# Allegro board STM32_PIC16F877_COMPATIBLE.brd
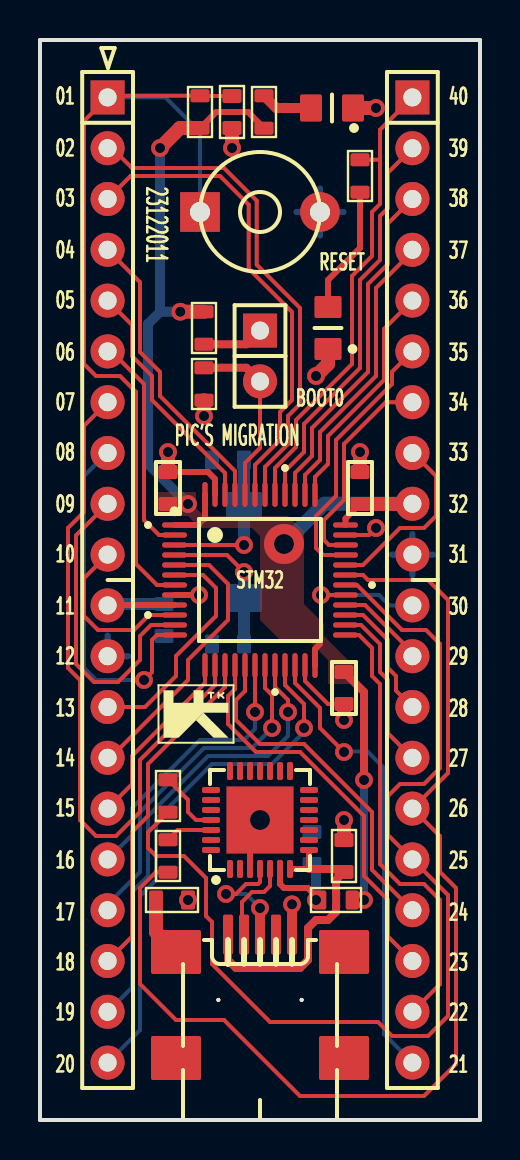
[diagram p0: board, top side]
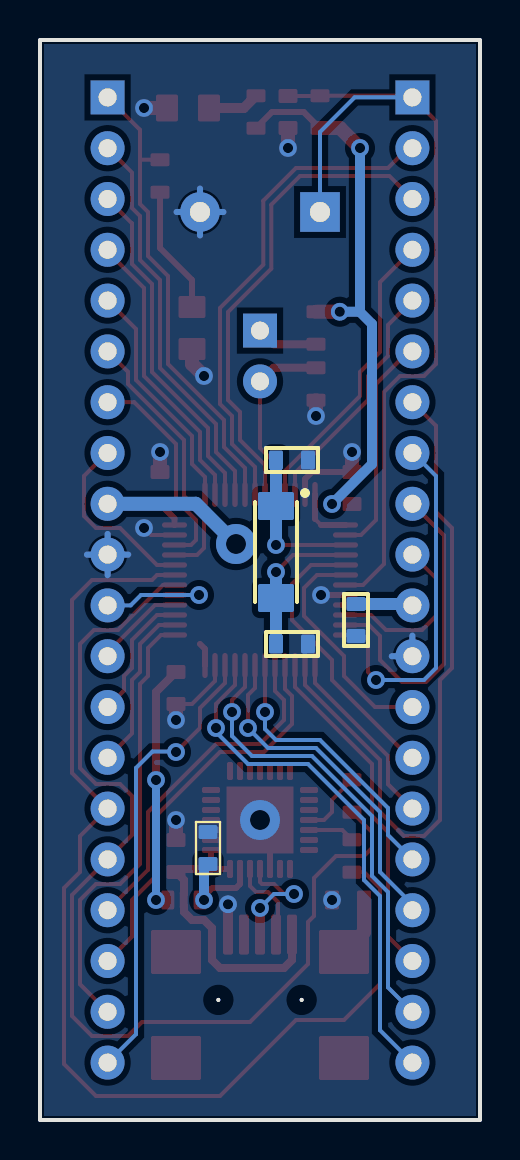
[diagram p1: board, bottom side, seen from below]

Outline 22 x 54 mm; copper layers: TOP, BOTTOM. Coordinates in mm from the lower left corner of the outline.
Outline path: 0,54 0,0 22,0 22,54 0,54

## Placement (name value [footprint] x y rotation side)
C1  100n  [CAP0603_B]  6.4 31.6 90 top
C2  100n  [CAP0603_B]  16 31.6 90 top
C3  100n  [CAP0603_B]  15.2 21.6 270 top
C4  100n  [CAP0603_B]  6.2 25 270 bottom
C5  15p  [CAP0603_B]  9.4 23.8 180 bottom
C6  15p  [CAP0603_B]  9.4 33 180 bottom
C7  10u  [CAP0603_B1]  13.6 13.6 90 bottom
C8  100n  [CAP0603_B1]  6.6 11 0 top
C9  10u  [CAP0603_B1]  15.2 13.2 90 top
C10  100n  [CAP0603_B1]  9.6 50.4 270 top
D1  LED  [LEDC2012X120M]  14.6 50.6 180 top
D2  LED  [LEDC2012X120M]  14.4 39.6 90 top
J1  CON20  [HDR254M-1X20]  3.38 51.13 270 top
J2  CON20  [HDR254M-1X20]  18.62 51.13 270 top
J3  USB_MB  [HIROSE-US60-MB-5ST]  11 0 0 top
J4  CON2  [HDR254M-1X2]  11 39.47 270 top
NOREF  -  []  5.92 18.86 0 top
NOREF#2  -  []  24 0 90 top
NOREF#3  -  []  0 56 0 top
R1  39R  [RES0603_B1]  6.4 13.2 270 top
R2  39R  [RES0603_B1]  6.4 16.2 270 top
R3  330R  [RES0603_B1]  11.2 50.4 90 top
R4  0R  [RES0603_B1]  14.8 11 0 top
R5  1K  [RES0603_B1]  8.2 39.6 270 top
R6  10K  [RES0603_B1]  8.2 36.8 270 top
R7  10K  [RES0603_B1]  8 50.4 90 top
R8  330R  [RES0603_B1]  16 47.2 270 top
S1  BT  [BUTTON_RST_CIRCLE]  11 45.4 0 top
U1  STM32F100  [LQFP48L]  11 27 0 top
U2  -  [CP2102]  11 15 90 top
Y1  32.768KHz  [ABS10]  10.2 28.4 270 bottom

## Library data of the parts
C1-C10 = C1005_0: User Part Number: pn; Tolerance: RichardLC
D1 D2 = LED_0: User Part Number: pn; Tolerance: RichardLC
J1 J2 = CON20: User Part Number: pn; Tolerance: RichardLC
J3 = CON9_2: User Part Number: pn; Tolerance: RichardLC
J4 = CON2: User Part Number: pn; Tolerance: RichardLC
R1-R8 = R_0: User Part Number: pn; Tolerance: RichardLC
S1 = SW PUSHBUTTON_1: User Part Number: pn; Tolerance: RichardLC
U1 = STM32F100_1: User Part Number: pn; Tolerance: RichardLC
U2 = CP2102_2: User Part Number: pn; Tolerance: RichardLC
Y1 = ZTA: User Part Number: pn; Tolerance: RichardLC

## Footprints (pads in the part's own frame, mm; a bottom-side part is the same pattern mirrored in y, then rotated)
ABS10
  custom 0.35x0.35 smd: 1(-2.3,0) 2(2.3,0)
BUTTON_RST_CIRCLE
  rect 1.98x1.98 hole 1: 1(-3,0)
  round 1.98 hole 1: 2(3,0)
CAP0603_B
  custom 0.175x0.175 smd: 1(-0.8,0) 2(0.8,0)
CAP0603_B1
  custom 0.175x0.175 smd: 1(-0.8,0) 2(0.8,0)
CP2102
  custom 0.075x0.075 smd: 1(-2.45,1.5) 2(-2.45,1) 3(-2.45,0.5) 4(-2.45,0) 5(-2.45,-0.5) 6(-2.45,-1) 7(-2.45,-1.5) 8(-1.5,-2.45) 9(-1,-2.45) 10(-0.5,-2.45) 11(0,-2.45) 12(0.5,-2.45) 13(1,-2.45) 14(1.5,-2.45) 15(2.45,-1.5) 16(2.45,-1) 17(2.45,-0.5) 18(2.45,0) 19(2.45,0.5) 20(2.45,1) 21(2.45,1.5) 22(1.5,2.45) 23(1,2.45) 24(0.5,2.45) 25(0,2.45) 26(-0.5,2.45) 27(-1,2.45) 28(-1.5,2.45)
  rect 3.35x3.35 smd: 29(0,0)
HDR254M-1X2
  rect 1.7x1.7 hole 0.9: 1(0,0)
  round 1.7 hole 0.9: 2(2.54,0)
HDR254M-1X20
  rect 1.7x1.7 hole 0.9: 1(0,0)
  round 1.7 hole 0.9: 2(2.54,0) 3(5.08,0) 4(7.62,0) 5(10.16,0) 6(12.7,0) 7(15.24,0) 8(17.78,0) 9(20.32,0) 10(22.86,0) 11(25.4,0) 12(27.94,0) 13(30.48,0) 14(33.02,0) 15(35.56,0) 16(38.1,0) 17(40.64,0) 18(43.18,0) 19(45.72,0) 20(48.26,0)
HIROSE-US60-MB-5ST
  round 0.2 hole 0.9 unplated: (-2.083,6.005) (2.083,6.005)
  custom 0.125x0.125 smd: 1(-1.6,9.271) 2(-0.8,9.271) 3(0,9.271) 4(0.8,9.271) 5(1.6,9.271)
  custom 0.55x0.55 smd: 6(-4.2,3.1) 7(4.2,3.1) 8(-4.2,8.4) 9(4.2,8.4)
LEDC2012X120M
  custom 0.275x0.275 smd: A(1.05,0) C(-1.05,0)
LQFP48L
  oval 1.25x0.27 smd: 1(-4.275,2.75) 2(-4.275,2.25) 3(-4.275,1.75) 4(-4.275,1.25) 5(-4.275,0.75) 6(-4.275,0.25) 7(-4.275,-0.25) 8(-4.275,-0.75) 9(-4.275,-1.25) 10(-4.275,-1.75) 11(-4.275,-2.25) 12(-4.275,-2.75) 25(4.275,-2.75) 26(4.275,-2.25) 27(4.275,-1.75) 28(4.275,-1.25) 29(4.275,-0.75) 30(4.275,-0.25) 31(4.275,0.25) 32(4.275,0.75) 33(4.275,1.25) 34(4.275,1.75) 35(4.275,2.25) 36(4.275,2.75)
  oval 0.27x1.25 smd: 13(-2.75,-4.275) 14(-2.25,-4.275) 15(-1.75,-4.275) 16(-1.25,-4.275) 17(-0.75,-4.275) 18(-0.25,-4.275) 19(0.25,-4.275) 20(0.75,-4.275) 21(1.25,-4.275) 22(1.75,-4.275) 23(2.25,-4.275) 24(2.75,-4.275) 37(2.75,4.275) 38(2.25,4.275) 39(1.75,4.275) 40(1.25,4.275) 41(0.75,4.275) 42(0.25,4.275) 43(-0.25,4.275) 44(-0.75,4.275) 45(-1.25,4.275) 46(-1.75,4.275) 47(-2.25,4.275) 48(-2.75,4.275)
RES0603_B1
  custom 0.163x0.163 smd: 1(-0.812,0) 2(0.812,0)

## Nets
GND: C1.2 C2.2 C3.2 C4.2 C5.2 C6.2 C7.2 C8.2 C9.2 C10.2 D1.C D2.C J1.12 J2.10 J3.5(GND) R6.2 S1.2 U1.8(VSSA) U1.23(VSS_1) U1.35(VSS_2) U1.47(VSS_3) U2.3(GND) U2.29(TM)
VDD1: C4.1 J1.11 U1.9(VDDA)
VDD2: C1.1 C2.1 C3.1 J2.9 R3.1 R4.2 R5.1 R7.1 U1.1(VBAT) U1.24(VDD_1) U1.36(VDD_2) U1.48(VDD_3)
BOOT0: J4.2 R6.1 U1.44(BOOT0)
NRST: C10.1 J1.1 R7.2 S1.1 U1.7(NRST)
OSC32_IN: C6.1 U1.3(PC14/OSC32_IN) Y1.1
OSC32_OUT: C5.1 U1.4(PC15/OSC32_OUT) Y1.2
OSC_IN: J1.14 U1.5(PD0/OSC_IN)
OSC_OUT: J1.13 U1.6(PD1/OSC_OUT)
PA0: J1.10 U1.10(PA0/WKUP)
PA1: J1.9 U1.11(PA1)
PA2: J1.8 U1.12(PA2)
PA3: J1.15 U1.13(PA3)
PA4: J1.7 U1.14(PA4)
PA5: J1.18 U1.15(PA5)
PA6: J2.18 U1.16(PA6)
PA7: J2.17 U1.17(PA7)
PA8: J2.11 U1.29(PA8)
PA9: J2.16 R2.2 U1.30(PA9)
PA10: J2.15 R1.2 U1.31(PA10)
PA11: J2.8 U1.32(PA11)
PA12: J2.6 U1.33(PA12)
PA13: J2.7 U1.34(PA13)
PA14: J2.5 U1.37(PA14)
PA15: J2.4 U1.38(PA15)
PB0: J1.16 U1.18(PB0)
PB1: J1.17 U1.19(PB1)
PB2: J1.19 U1.20(PB2)
PB3: J2.3 U1.39(PB3)
PB4: J2.2 U1.40(PB4)
PB5: J2.1 R8.1 U1.41(PB5)
PB6: J1.2 U1.42(PB6)
PB7: J1.3 U1.43(PB7)
PB8: J1.4 U1.45(PB8)
PB9: J1.5 U1.46(PB9)
PB10: J1.20 U1.21(PB10)
PB11: J2.20 U1.22(PB11)
PB12: J2.19 U1.25(PB12)
PB13: J2.14 U1.26(PB13)
PB14: J2.13 U1.27(PB14)
PB15: J2.12 U1.28(PB15)
PC13: J1.6 U1.2(PC13/TAMPER/RTC)
UART_3V3: C7.1 R4.1 U2.6(VDD)
N15023592: C9.1 J3.1(VBUS) U2.7(REGIN) U2.8(VBUS)
N15023612: J3.3(DP) U2.4(D+)
N15023760: R1.1 U2.26(TXD)
N15023764: R2.1 U2.25(RXD)
N15029027: C8.1 J3.8(SH3)
N15029202: J4.1 R5.2
N15033163: J3.2(DM) U2.5(D-)
N150239201: D1.A R3.2
N150311720: D2.A R8.2

Pads without a net: J3 4 6 7 9; U2 1 2 9 10 11 12 13 14 15 16 17 18 19 20 21 22 23 24 27 28

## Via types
v1: diameter 0.889, hole 0.508, TOP to BOTTOM, 29 vias
v2: diameter 2, hole 1, TOP to BOTTOM, 2 vias

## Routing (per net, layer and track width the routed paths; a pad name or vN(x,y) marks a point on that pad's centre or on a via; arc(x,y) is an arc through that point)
GND: length 32.7
  TOP w0.2: v1(16.8,29.6) 16.45,29.25 U1.35 ; C3.2 14.4,20.8 13.25,21.95 U1.23
  TOP w0.3: C1.2 8.4,32.4 8.75,32.05 U1.47 ; v2(11,15) 10.5,14.5 U2.3 ; U1.8 v1(7.95,26.25)
  TOP w0.5: J3.5 v1(12.6,10.79)
  TOP w0.7: C3.2 v1(15.2,20) ; C1.2 v1(6.4,33.4) ; C10.2 v1(9.6,48.6) ; D2.C 14.4,37.8 v1(13.8,37.2) ; D1.C v1(16.8,50.6) ; C2.2 v1(16,33.4) ; C9.2 v1(15.2,15) ; R6.2 v1(8.2,35.2)
  BOTTOM w0.305: J2.10 18.62,29.3 ; J2.10 19.65,28.27 ; J2.10 18.62,27.24 ; J2.10 17.59,28.27 ; 12.83,45.4 S1.2 ; S1.2 14,44.23 ; S1.2 14,46.57 ; S1.2 15.17,45.4 ; 3.38,24.22 J1.12 4.41,23.19
  vias: v1(7.4,11)
VDD1: length 6.2
  TOP w0.3: U1.9 3.4,25.75 J1.11
  BOTTOM w0.6: C4.1 3.45,25.8 J1.11
VDD2: length 55.1
  TOP w0.2: 7.95,29.75 8.25,30.05
  TOP w0.3: 8.25,30.05 U1.48 ; U1.36 15.28,30.07 C2.1 ; U1.24 13.75,23.55 14,23.8 ; U1.1 7.95,29.75 ; R7.1 8.81,50.4 10.4,50.4 11.2,49.6 R3.1
  TOP w0.4: v1(16.2,17) 16.2,21.4 C3.1
  TOP w0.5: R4.2 v1(16.2,11)
  TOP w0.7: J2.9 18.61,30.8 C2.1 ; v1(6,48.6) 7,49.6 7.99,49.6 R7.1 ; R5.1 v1(7.01,40.41)
  BOTTOM w0.2: 6,40.4 6.01,40.41
  BOTTOM w0.4: v1(16.2,11) v1(16.2,17)
  BOTTOM w0.5: v1(6,48.6) 6,40.4 5.4,39.8 5.4,32.8 v1(7.4,30.8) ; 6.01,40.41 v1(7.01,40.41)
  BOTTOM w0.7: v2(12.2,28.8) 14.21,30.81 J2.9
BOOT0: length 9
  TOP w0.2: U1.44 10.25,32.85 11,33.6 J4.2
  TOP w0.4: J4.2 10.32,37.61 R6.1
NRST: length 43.6
  TOP w0.2: C10.1 8.01,51.2 R7.2 3.46,51.21 J1.1 2.2,49.95 2.2,37.8 2.8,37.2 4,37.2 4.8,36.4 4.8,27.8 5.85,26.75 U1.7
  BOTTOM w0.2: S1.1 8,49.4 6.27,51.13 J1.1
OSC32_IN: length 7.7
  TOP w0.2: U1.3 v1(10.2,28.75)
  BOTTOM w0.6: v1(10.2,28.75) Y1.1 C6.1
OSC32_OUT: length 7.4
  TOP w0.2: U1.4 9.35,28.25 v1(10.2,27.4)
  BOTTOM w0.6: C5.1 Y1.2 v1(10.2,27.4)
OSC_IN: length 14.3
  TOP w0.2: J1.14 3.51,18.11 7.4,22 7.4,23 9.4,25 9.4,26.8 8.45,27.75 U1.5
OSC_OUT: length 11.6
  TOP w0.2: J1.13 5.25,20.65 6.8,22.2 6.8,23.2 8.8,25.2 8.8,26.6 8.15,27.25 U1.6
PA0: length 8.7
  TOP w0.2: J1.10 2.2,27.09 2.2,25.2 2.9,24.5 4.7,24.5 5.45,25.25 U1.10
PA1: length 15.8
  TOP w0.2: U1.11 5.55,24.75 5,24.2 5,23 3.9,21.9 2.7,21.9 1.8,22.8 1.8,29.23 J1.9
PA2: length 17.9
  TOP w0.2: U1.12 5.85,24.25 5.6,24 5.6,22.4 v1(5.2,22)
  BOTTOM w0.2: J1.8 3.35,33.35 2.2,32.2 2.2,22.6 2.8,22 v1(5.2,22)
PA3: length 9.2
  TOP w0.2: U1.13 8.25,21.85 4.6,18.2 4.6,16.79 J1.15
PA4: length 34.7
  TOP w0.2: J1.7 2.2,34.71 2.2,30.4 1.4,29.6 1.4,22.6 2,22 2,15 2.8,14.2 3.8,14.2 5,15.4 5,18 8.75,21.75 U1.14
PA5: length 17.2
  TOP w0.2: J1.18 4.6,9.17 4.6,14.4 5.4,15.2 5.4,17.8 9.25,21.65 U1.15
PA6: length 20
  TOP w0.2: U1.16 9.75,21.55 9.4,21.2 9.4,19.8 10.8,18.4 13,18.4 16.2,15.2 16.2,12.2 17.4,11 17.4,9.17 J2.18
PA7: length 17.4
  TOP w0.2: U1.17 10.25,21.45 9.8,21 9.8,20 11,18.8 13.2,18.8 16.6,15.4 16.6,12.51 J2.17
PA8: length 6
  TOP w0.2: U1.29 v1(14.05,26.25)
  BOTTOM w0.2: v1(14.05,26.25) 16.95,26.25 17.47,25.73 J2.11
PA9: length 51.4
  TOP w0.2: U1.30 15.85,26.75 18.1,24.5 19.3,24.5 20,23.8 20,17.6 19.2,16.8 18,16.8 17.4,16.2 17.4,14.25 J2.16 20.4,11.25 20.4,5.2 19.4,4.2 17.6,4.2 16.9,4.9 11.5,4.9 8.6,7.8 8.6,9.9 8.3,10.2 8.3,12.1 7.2,13.2 5.8,13.2 5.4,13.6 5.4,14.39 R2.2
PA10: length 55.8
  TOP w0.2: R1.2 5.79,12.39 5,11.6 5,6.8 6.8,5 9.2,5 13,1.2 19.2,1.2 20.8,2.8 20.8,11.6 20,12.4 20,14.19 J2.15 20.4,17.35 20.4,26 19.4,27 16.4,27 16.15,27.25 U1.31
PA11: length 9.2
  TOP w0.2: U1.32 16.15,27.75 18,29.6 19.2,29.6 19.8,30.2 19.8,32.2 18.65,33.35 J2.8
PA12: length 13.4
  TOP w0.2: U1.33 14.15,28.25 13.8,28.6 13.8,30.2 14.8,31.2 14.8,34 17.6,36.8 17.6,37.41 J2.6
PA13: length 10.7
  TOP w0.2: J2.7 17.29,35.89 15.2,33.8 15.2,31 14.2,30 14.2,29 14.45,28.75 U1.34
PA14: length 11.7
  TOP w0.2: J2.5 17.2,39.55 17.2,37 14.4,34.2 14.4,32.8 13.75,32.15 U1.37
PA15: length 14.5
  TOP w0.2: J2.4 18.62,43.42 16.8,41.6 16.8,37.2 14,34.4 14,33 13.25,32.25 U1.38
PB0: length 14
  TOP w0.2: U1.18 v1(10.75,20.4)
  BOTTOM w0.2: J1.16 4.6,14.25 4.6,15.6 8,19 10.2,19 10.75,19.55 v1(10.75,20.4)
PB1: length 17.2
  TOP w0.2: U1.19 11.25,21.6 11.6,21.25 v1(11.6,19.6)
  BOTTOM w0.2: J1.17 3.38,10.78 5,12.4 5,15.4 8.2,18.6 10.6,18.6 v1(11.6,19.6)
PB2: length 23.1
  TOP w0.2: v1(12.4,20.4) 12.4,21 11.75,21.65 U1.20
  BOTTOM w0.2: J1.19 4.6,6.63 4.6,11.4 5.4,12.2 5.4,15.2 8.4,18.2 11.4,18.2 12.4,19.2 v1(12.4,20.4)
PB3: length 17.2
  TOP w0.2: J2.3 17.4,44.83 17.4,42.8 16.4,41.8 16.4,37.4 13.6,34.6 13.6,33.2 12.75,32.35 U1.39
PB4: length 20
  TOP w0.2: U1.40 12.25,32.45 13.2,33.4 13.2,34.8 16,37.6 16,42 17,43 17,45.2 17.4,45.6 17.4,47.37 J2.2
PB5: length 23.7
  TOP w0.2: U1.41 11.75,32.6 12.8,33.65 12.8,35 15.6,37.8 15.6,42.2 16.6,43.2 16.6,45.4 17,45.8 17,48 ; R8.1 16.99,48.01 17,48 ; 17,48 17,49.51 J2.1
PB6: length 24.9
  TOP w0.2: U1.42 11.25,32.65 12.4,33.8 12.4,35.2 13,35.8 13,40.6 10.84,42.76 10.84,45.96 9.2,47.6 4.6,47.6 3.61,48.59 J1.2
PB7: length 24.3
  TOP w0.2: U1.43 10.75,32.75 12,34 12,35.4 12.6,36 12.6,40.4 10.44,42.56 10.44,45.76 9,47.2 4.53,47.2 J1.3
PB8: length 14.9
  TOP w0.2: J1.4 5,41.89 5,38.4 6,37.4 6,36.2 9.75,32.45 U1.45
PB9: length 12.1
  TOP w0.2: J1.5 4.6,39.75 4.6,38.2 5.6,37.2 5.6,36 9.25,32.35 U1.46
PB10: length 26.1
  TOP w0.2: U1.21 12.25,21.75 13.2,20.8 v1(13.2,19.6)
  BOTTOM w0.2: J1.20 5,4.49 5,11.2 5.8,12 5.8,15 8.6,17.8 11.6,17.8 13.2,19.4 v1(13.2,19.6)
PB11: length 23
  TOP w0.2: U1.22 12.75,21.85 14,20.6 14,19.6 v1(15.2,18.4)
  BOTTOM w0.2: v1(15.2,18.4) 15.22,18.43 16.38,18.43 17.2,17.6 17.2,4.29 J2.20
PB12: length 22.5
  TOP w0.2: U1.25 15.95,24.25 16.6,23.6 16.6,22.2 17,21.8 17,12.8 18,11.8 19.2,11.8 20,11 20,6.79 J2.19
PB13: length 8.5
  TOP w0.2: U1.26 16.05,24.75 17,23.8 17,22.4 17.4,22 17.4,19.33 J2.14
PB14: length 6.5
  TOP w0.2: U1.27 16.15,25.25 17.4,24 17.4,22.6 17.8,22.2 17.8,21.47 J2.13
PB15: length 4.5
  TOP w0.2: J2.12 18.62,23.38 16.25,25.75 U1.28
PC13: length 11.1
  TOP w0.2: U1.2 5.95,29.25 5.2,30 5.2,36.8 3.57,38.43 J1.6
UART_3V3: length 5.1
  TOP w0.2: R4.1 v1(13.8,11)
  TOP w0.3: R4.1 13.39,11.6 12.2,11.6 12,11.8 U2.6
  BOTTOM w0.5: v1(13.8,11) 13.8,12.6 C7.1
N15023592: length 14.8
  TOP w0.3: U2.7 13.45,12.55 U2.8
  TOP w0.4: 13.45,12.55 15.05,12.55 C9.1 14.8,12 14.8,11.35 14.81,11.34 14.81,10.66 14.8,10.65 14.8,10.4 14.4,10 13.8,10 13.4,9.6 13.4,8 13,7.6 9.8,7.6 9.4,8 J3.1
N15023612: length 5.9
  TOP w0.2: U2.4 11,11.9 10.9,11.8 10.3,11.8 9.8,11.3 v1(9.3,11.3) ; J3.3 v1(11,10.6)
  BOTTOM w0.2: v1(11,10.6) 10.3,11.3 v1(9.3,11.3)
N15023760: length 2.4
  TOP w0.2: U2.26 6.89,14.5 R1.1
N15023764: length 3.3
  TOP w0.2: U2.25 7.8,15 7.4,15.4 7.4,16.01 R2.1
N15029027: length 3
  TOP w0.7: J3.8 5.8,9.4 C8.1
N15029202: length 3.1
  TOP w0.4: R5.2 10.32,38.79 J4.1
N15033163: length 4.3
  TOP w0.2: U2.5 11.5,11.7 11.2,11.4 10.6,11.4 10.1,10.9 10.1,9.37 J3.2
N150239201: length 2.6
  TOP w0.5: R3.2 11.81,50.6 D1.A
N150311720: length 6.4
  TOP w0.3: R8.2 16,43.6 14.4,42 D2.A

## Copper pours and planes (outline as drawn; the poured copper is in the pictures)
GND on BOTTOM: 0.2,53.8 0.2,0.2 21.8,0.2 21.8,53.8
VDD2 on TOP: 8,29.6 10.6,29.6 11,29.2 11,25 12,24 13.4,24 14.4,23 14.4,21.8 15.8,21.8 15.8,23 15.4,23 14.2,24.2 14.2,24.8 13.2,25.8 13.2,29.4 12.4,30.2 8.2,30.2 7.8,30.6 7.8,31.4 5.8,31.4 5.8,30.2 7.4,30.2

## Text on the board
Ref Des/Silkscreen Top: 01 | 02 | 03 | 04 | 05 | 06 | 07 | 08 | 09 | 10 | 11 | 12 | 13 | 14 | 15 | 16 | 17 | 18 | 19 | 20 | 40 | 39 | 38 | 37 | 36 | 35 | 34 | 33 | 32 | 31 | 30 | 29 | 28 | 27 | 26 | 25 | 24 | 23 | 22 | 21 | STM32 | BOOT0 | RESET | PIC'S MIGRATION | 23122011
COMPVAL_TYPE_TOP: FIGURE | SIZE | 0.508 | 0.9 | 1.0 | DRILL CHART: TOP to BOTTOM | ALL UNITS ARE IN MILLIMETERS | PLATED | NON-PLATED | QTY | 29 | 42 | 2
